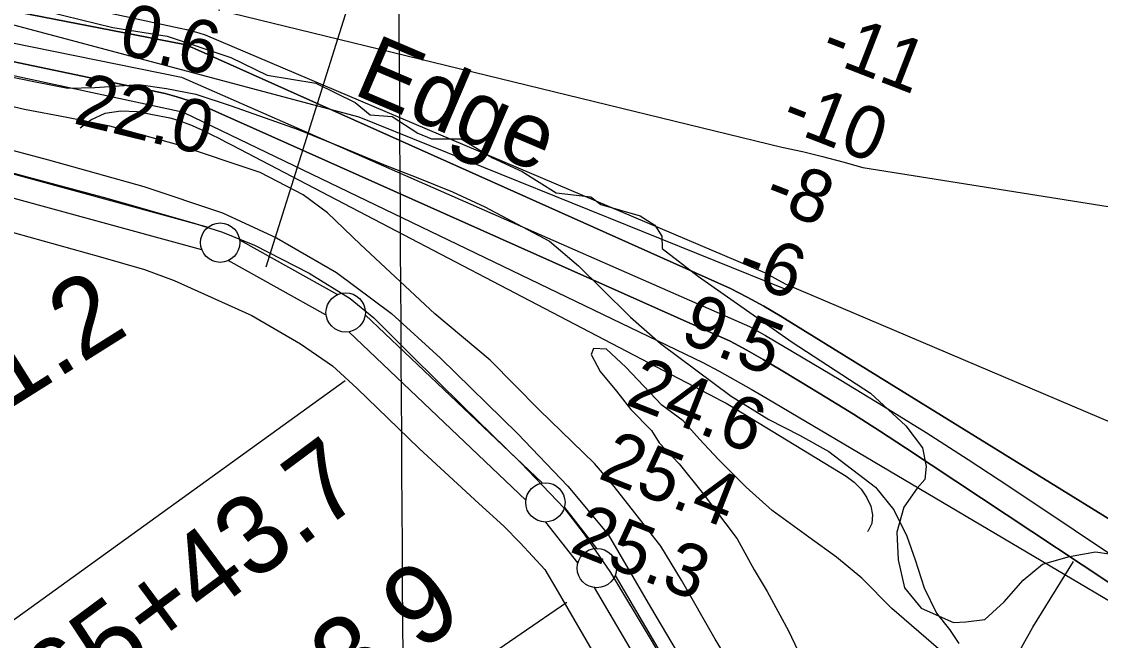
# Model space of a CAD drawing. Extents: x 3477039 to 3515015, y 546746 to 572297.
# Drawn here: x 3496548 to 3497919, y 562259 to 563045 of the extents above; entities that cross this region are included whole.
import ezdxf

# ---------------------------------------------------------------- set-up
doc = ezdxf.new("R2010")
doc.units = 0
for name, color, linetype in [('V-FLOD-BASE', 7, 'Continuous'), ('V-GRID-MAJR', 7, 'Continuous'), ('V-LEVE-TOET', 7, 'Continuous'), ('V-RIVR-EDGE', 7, 'Continuous'), ('V-RIVR-IDEN', 7, 'Continuous'), ('V-RIVR-RANG', 7, 'Continuous'), ('V-ROAD-CNTR', 7, 'Continuous'), ('V-RRAP-FSHR', 7, 'Continuous'), ('V-SITE-VEGE', 7, 'Continuous'), ('V-SURV-IDEN', 7, 'Continuous'), ('V-SURV-LINE', 7, 'Continuous'), ('V-TOPO-DPTH', 7, 'Continuous'), ('V-TOPO-MINR', 7, 'Continuous'), ('V-TOPO-SHOR', 7, 'Continuous'), ('V-TOPO-WATR', 7, 'Continuous')]:
    doc.layers.add(name, color=color, linetype=linetype)

msp = doc.modelspace()

# ---------------------------------------------------------------- linework, layer by layer
at = {"layer": 'V-FLOD-BASE'}
msp.add_lwpolyline([(3496072.208, 562978.024), (3496198.731, 562942.932), (3496343.41, 562904.79), (3496508.679, 562860.148), (3496656.299, 562821.006), (3496768.595, 562788.941), (3496803.407, 562777.941), (3496844.078, 562761.012), (3496913.6240000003, 562725.748), (3496965.506, 562693.531), (3496995.821, 562668.801), (3497043.197, 562621.384), (3497108.16, 562557.169), (3497182.41, 562484.549), (3497238.077, 562426.77), (3497262.943, 562394.213), (3497296.559, 562345.399), (3497348.136, 562259.156), (3497396.784, 562175.876), (3497451.286, 562085.197), (3497489.725, 562020.638), (3497518.917, 561971.357), (3497528.301, 561980.636)], dxfattribs=at)
at = {"layer": 'V-GRID-MAJR'}
msp.add_spline([(3497073.037565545, 555496.0515890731), (3497056.56, 558259.177), (3497020.416, 564320.132), (3496984.272, 570381.104), (3496984.251, 570384.554)], degree=3, dxfattribs=at)
at = {"layer": 'V-LEVE-TOET'}
for points in [[(3495687.304, 563022.464), (3495831.693, 563028.606), (3495926.179, 563028.921), (3495972.9590000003, 563024.707), (3496046.356, 563009.4), (3496195.292, 562971.336), (3496374.8000000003, 562924.779), (3496582.252, 562869.745), (3496703.219, 562835.785), (3496803.19, 562802.384), (3496872.115, 562770.48), (3496947.965, 562726.2880000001), (3497018.085, 562674.257), (3497080.299, 562617.46), (3497178.154, 562521.957), (3497242.06, 562455.09), (3497293.311, 562393.546), (3497347.444, 562301.365), (3497421.936, 562175.383), (3497485.5840000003, 562065.21), (3497528.424, 561986.657)], [(3495981.995, 562925.794), (3496080.275, 562901.591), (3496182.9020000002, 562873.425), (3496314.361, 562838.527), (3496447.563, 562802.304), (3496648.447, 562746.437), (3496704.343, 562730.358), (3496741.877, 562716.136), (3496840.474, 562671.81), (3496902.377, 562636.011), (3496942.8880000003, 562607.777), (3496974.216, 562579.594), (3497053.376, 562503.013), (3497129.074, 562433.013), (3497160.832, 562403.956), (3497181.703, 562382.835), (3497212.9990000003, 562348.9670000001), (3497226.856, 562325.263), (3497280.116, 562233.525), (3497366.765, 562092.598), (3497411.8170000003, 562017.9670000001), (3497436.4930000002, 561974.955), (3497448.6210000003, 561954.76)]]:
    msp.add_lwpolyline(points, dxfattribs=at)
at = {"layer": 'V-RIVR-EDGE'}
msp.add_lwpolyline([(3496560.1901922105, 563063.4036298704), (3496663.983718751, 563037.933259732), (3496732.9941397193, 563026.9567374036), (3496813.9709404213, 562999.7418065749), (3496860.1408847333, 562977.4155561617), (3496921.9489145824, 562967.0571699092), (3496971.7148589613, 562942.3207210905), (3496990.886598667, 562926.6648224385), (3497019.097324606, 562924.7940855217), (3497051.462809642, 562903.702622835), (3497068.854362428, 562896.4556989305), (3497106.6747090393, 562896.3621800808), (3497146.2366474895, 562872.2512894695), (3497184.0139457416, 562854.7484047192), (3497227.170399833, 562827.6269927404), (3497271.5824236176, 562822.714561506), (3497284.1654550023, 562813.0782211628), (3497333.9566346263, 562798.5472626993), (3497352.536957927, 562786.4947862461), (3497361.5076605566, 562772.6650917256), (3497362.0693884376, 562757.0552102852), (3497408.206675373, 562721.5218547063), (3497527.464609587, 562637.7815621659), (3497626.959387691, 562573.3005904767), (3497671.881184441, 562531.7669741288), (3497692.8227200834, 562503.4998399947), (3497697.5674111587, 562480.0753690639), (3497695.7248783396, 562463.2707794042), (3497686.092991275, 562452.4887169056), (3497669.224571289, 562428.5173623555), (3497660.14105227, 562396.7225117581), (3497661.8544400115, 562361.2990037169), (3497670.171380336, 562325.8591669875), (3497691.1188536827, 562299.9933247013), (3497732.4966052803, 562281.8812104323), (3497748.106486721, 562282.4429383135), (3497772.126827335, 562285.3851760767), (3497796.7964769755, 562308.136587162), (3497820.877679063, 562335.6920663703), (3497845.5413909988, 562356.0421856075), (3497879.7835506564, 562365.5627407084), (3497912.8161578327, 562371.484326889), (3497947.6230142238, 562366.5956464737)], dxfattribs=at)
at = {"layer": 'V-RIVR-RANG'}
msp.add_line((3496858.6666, 562733.698), (3497123.1673, 563573.0069000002), dxfattribs=at)
at = {"layer": 'V-ROAD-CNTR'}
msp.add_lwpolyline([(3496878.1762055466, 561543.768886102), (3497110.424741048, 561698.6355763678), (3497343.9712739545, 561857.336258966), (3497474.2200134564, 561930.8751118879), (3497516.53792882, 561956.562060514), (3497550.804860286, 561982.9160078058), (3497648.600664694, 562052.7898680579), (3497701.835558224, 562092.0257895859), (3497726.6265086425, 562111.6957502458), (3497751.4764589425, 562136.2327011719), (3497777.678406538, 562176.387620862), (3497832.995295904, 562276.022421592), (3497884.8031922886, 562359.22825518)], dxfattribs=at)
at = {"layer": 'V-RRAP-FSHR'}
msp.add_lwpolyline([(3496209.8331950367, 563128.6671438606), (3496976.665835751, 562924.4241996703), (3497517.9563322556, 562705.5933514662)], dxfattribs=at)
at = {"layer": 'V-SITE-VEGE'}
for points in [[(3496530.38, 562975.956), (3496565.602, 562968.901), (3496606.693, 562960.836), (3496640.978, 562961.622), (3496696.829, 562965.224), (3496732.061, 562960.129), (3496769.24, 562953.0650000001), (3496814.2120000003, 562938.121), (3496899.258, 562908.257), (3496953.005, 562886.407), (3497007.7260000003, 562863.572), (3497051.707, 562846.674), (3497095.681, 562828.799), (3497136.715, 562809.955), (3497218.744, 562766.398), (3497255.786, 562734.8470000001), (3497285.009, 562706.279), (3497322.024, 562669.829), (3497360.0330000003, 562636.316), (3497449.768, 562569.207), (3497497.595, 562539.554), (3497536.663, 562519.746), (3497573.764, 562498.969), (3497633.257, 562453.579), (3497656.6040000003, 562425.042), (3497673.066, 562391.647), (3497683.668, 562361.224), (3497695.223, 562325.9), (3497710.7120000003, 562293.491), (3497727.248, 562272.828), (3497738.903, 562255.134)], [(3497452.715, 562222.462), (3497429.423, 562260.79), (3497386.747, 562335.471), (3497360.545, 562378.712), (3497327.48, 562421.0160000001), (3497301.225, 562454.466), (3497275.924, 562483.992), (3497205.786, 562551.969), (3497143.453, 562615.004), (3497073.2660000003, 562674.167), (3496978.751, 562761.87), (3496936.861, 562802.263), (3496905.645, 562824.9670000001), (3496850.955, 562853.678), (3496743.417, 562889.545), (3496660.293, 562912.54), (3496605.503, 562923.621), (3496551.691, 562933.718), (3496511.583, 562942.76)], [(3497713.399, 562248.42), (3497653.9390000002, 562299.686), (3497615.955, 562338.098), (3497583.7830000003, 562364.724), (3497548.67, 562390.39), (3497501.843, 562423.952), (3497468.7060000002, 562453.523), (3497433.644, 562488.983), (3497409.304, 562514.585), (3497388.867, 562538.206), (3497361.5530000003, 562557.949), (3497315.788, 562606.2000000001), (3497291.429, 562628.865), (3497274.785, 562629.938), (3497271.8030000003, 562622.1190000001), (3497283.436, 562600.504), (3497303.865, 562575.904), (3497322.342, 562552.292), (3497348.6380000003, 562525.699), (3497358.345, 562509.975), (3497383.661, 562483.387), (3497412.841, 562446.982), (3497457.565, 562387.963), (3497478.8910000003, 562348.664), (3497495.387, 562321.147), (3497522.532, 562271.041), (3497554.4760000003, 562204.257)]]:
    msp.add_lwpolyline(points, dxfattribs=at)
at = {"layer": 'V-SURV-LINE'}
for points in [[(3496037.8723756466, 562988.4080392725), (3496784.9746972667, 562784.142716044)], [(3496777.0595025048, 562755.2057206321), (3496029.956636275, 562959.4711927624)], [(3496825.0244797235, 562767.8216314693), (3496949.6372057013, 562698.5999764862)], [(3496935.07870085, 562672.3692682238), (3496810.4658875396, 562741.5909717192)], [(3496984.631403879, 562672.8888537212), (3497209.4488662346, 562459.0803386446)], [(3497188.7864359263, 562437.3302986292), (3496963.9692479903, 562651.1385527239)], [(3497237.7426249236, 562427.9564077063), (3497278.558338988, 562375.9210310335)], [(3497254.940077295, 562357.4229719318), (3497214.1248192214, 562409.457767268)], [(3497302.133959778, 562341.3218390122), (3497646.563880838, 561754.9311758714)], [(3497620.6985608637, 561739.7329770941), (3497276.2689325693, 562326.1231418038)]]:
    msp.add_lwpolyline(points, dxfattribs=at)
for centre in [(3496800.28232, 562764.4068499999), (3496959.82085, 562675.7841300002), (3497213.59695, 562434.43472), (3497279.08556, 562350.9440500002)]:
    msp.add_circle(centre, 25, dxfattribs=at)
at = {"layer": 'V-TOPO-DPTH'}
for points in [[(3497951.1001583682, 562400.5103058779), (3497512.086101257, 562671.5413076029), (3497491.3229211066, 562683.5701052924), (3497470.2713532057, 562695.0867503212), (3497449.027526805, 562706.2619602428), (3496768.555811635, 563010.6883370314), (3496764.688684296, 563012.2789411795), (3496760.792792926, 563013.7921050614), (3496756.8537555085, 563015.1891085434), (3496752.8859540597, 563016.5086717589), (3496022.100627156, 563159.0706898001)], [(3496022.100627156, 563159.0706898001), (3496752.8859540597, 563016.5086717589), (3496756.8537555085, 563015.1891085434), (3496760.792792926, 563013.7921050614), (3496764.688684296, 563012.2789411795), (3496768.555811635, 563010.6883370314), (3497449.027526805, 562706.2619602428), (3497470.2713532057, 562695.0867503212), (3497491.3229211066, 562683.5701052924), (3497512.086101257, 562671.5413076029), (3497951.1001583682, 562400.5103058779)], [(3498319.7745268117, 562045.668540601), (3498313.5190530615, 562051.2428822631), (3498082.5051031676, 562230.2756945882), (3498076.1257527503, 562235.1061265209), (3498069.6767550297, 562239.8394009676), (3498063.123286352, 562244.4269391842), (3498056.5001703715, 562248.9173199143), (3497671.3673842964, 562503.7774280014), (3497638.2959532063, 562525.3273420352), (3497605.026394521, 562546.5619391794), (3497571.459644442, 562567.3235609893), (3497537.6947667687, 562587.7698659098), (3497511.1291651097, 562603.6007996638), (3497490.419214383, 562615.755113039), (3497469.603695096, 562627.7229340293), (3497448.629822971, 562639.4110164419), (3496774.9620149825, 562939.8991478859), (3496760.1951653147, 562944.9643186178), (3496745.3287497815, 562949.6977768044), (3496730.31298545, 562953.9336661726), (3495961.836846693, 563115.1532687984)], [(3496798.264202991, 563060.3077159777), (3497514.3571759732, 562885.9203614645), (3497540.223596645, 562880.2632503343), (3497565.9590105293, 562874.0936762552), (3497591.49791423, 562867.1554077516), (3497616.9058111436, 562859.7046762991), (3498389.7032243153, 562737.2775372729)], [(3496798.264202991, 563060.3077159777), (3497514.3571759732, 562885.9203614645), (3497540.223596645, 562880.2632503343), (3497565.9590105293, 562874.0936762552), (3497591.49791423, 562867.1554077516), (3497616.9058111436, 562859.7046762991), (3498389.7032243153, 562737.2775372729)]]:
    msp.add_lwpolyline(points, dxfattribs=at)
at = {"layer": 'V-TOPO-MINR'}
for points in [[(3495962.5593857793, 563206.8497661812), (3496749.5225480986, 563036.992589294), (3496757.5021655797, 563035.0802353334), (3496765.4532829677, 563033.0602953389), (3496773.361650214, 563030.8789762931), (3496781.241517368, 563028.5900712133), (3497492.154394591, 562726.3530113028), (3497505.335423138, 562719.2565741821), (3497518.400462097, 562711.9487913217), (3498210.8662024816, 562417.9298854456), (3498809.7839322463, 562018.7499259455), (3498836.3322918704, 561999.9304653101), (3498862.790504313, 561980.9860429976), (3498889.1134959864, 561961.854178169), (3499795.129970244, 561510.7892343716), (3499807.621747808, 561498.2787757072), (3499819.8414169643, 561485.4874467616), (3499910.6355924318, 561387.2314009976), (3499968.329494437, 561325.3693341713), (3500026.3989855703, 561263.865164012), (3500392.8703155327, 560889.0486487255)], [(3495964.296088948, 563134.9125580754), (3496751.2371467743, 562974.5651640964), (3497473.002544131, 562657.7323242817), (3497479.915492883, 562654.0448458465), (3497486.749094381, 562650.2123208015), (3497493.5297977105, 562646.2830980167), (3497589.178619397, 562589.5007085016), (3497643.472841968, 562556.6775003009), (3497697.405709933, 562523.2810427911), (3497750.796545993, 562489.0247113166), (3497803.8260274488, 562454.1951305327), (3498047.920982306, 562291.0600016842)], [(3495961.836846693, 563115.1532687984), (3496730.31298545, 562953.9336661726), (3496745.3287497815, 562949.6977768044), (3496760.1951653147, 562944.9643186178), (3496774.9620149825, 562939.8991478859), (3497448.629822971, 562639.4110164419), (3497469.603695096, 562627.7229340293), (3497490.419214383, 562615.755113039), (3497511.1291651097, 562603.6007996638), (3497537.6947667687, 562587.7698659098), (3497571.459644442, 562567.3235609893), (3497605.026394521, 562546.5619391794), (3497638.2959532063, 562525.3273420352), (3497671.3673842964, 562503.7774280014), (3498056.5001703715, 562248.9173199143), (3498063.123286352, 562244.4269391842), (3498069.6767550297, 562239.8394009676), (3498076.1257527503, 562235.1061265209), (3498082.5051031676, 562230.2756945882), (3498313.5190530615, 562051.2428822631), (3498319.7745268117, 562045.668540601)], [(3496006.3622241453, 563091.7372108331), (3496748.200157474, 562931.4640090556), (3496754.904706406, 562929.3111532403), (3497413.7817678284, 562612.3123601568), (3497434.3342412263, 562601.1038314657), (3497454.7933469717, 562589.7297403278), (3497475.112401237, 562578.1073055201), (3497495.338087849, 562566.3193082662), (3497989.835469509, 562274.065703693)], [(3496798.264202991, 563060.3077159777), (3497514.3571759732, 562885.9203614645), (3497540.223596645, 562880.2632503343), (3497565.9590105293, 562874.0936762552), (3497591.49791423, 562867.1554077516), (3497616.9058111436, 562859.7046762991), (3498389.7032243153, 562737.2775372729)], [(3496622.203805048, 562910.2959228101), (3496636.144251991, 562920.4585767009), (3496654.204244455, 562929.0242253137), (3496673.9788358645, 562931.9395638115), (3496694.8964932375, 562931.0880288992), (3496736.461010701, 562922.9531846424), (3496741.103116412, 562921.7148133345), (3496751.4724252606, 562918.1847953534), (3496757.7495556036, 562915.9171052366), (3496763.9640263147, 562913.4969398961), (3496770.0845075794, 562910.8480617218), (3496776.1423292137, 562908.0467083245), (3496781.324696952, 562905.5324876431), (3496789.9075728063, 562901.3215939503), (3496798.465139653, 562897.06043046), (3496806.984742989, 562892.723862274), (3496815.479037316, 562888.3370242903), (3497430.1624055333, 562567.4407016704), (3497436.7757662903, 562563.9042661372), (3497443.3403592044, 562560.2814968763), (3497449.831800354, 562556.5292270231), (3497456.27447366, 562552.6906234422), (3497596.0204015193, 562467.5391097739), (3497606.0746052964, 562459.9238100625), (3497614.870348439, 562451.2624218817), (3497621.778400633, 562441.0319009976), (3497627.4279921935, 562429.7552916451), (3497629.295909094, 562418.3612826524), (3497628.5308588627, 562407.6779660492), (3497623.8163579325, 562398.0606880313), (3497623.1482207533, 562397.2507735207)]]:
    msp.add_lwpolyline(points, dxfattribs=at)
at = {"layer": 'V-TOPO-SHOR'}
for p, q in [((3496518.674816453, 562271.4665421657), (3496959.2386911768, 562589.2503206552)), ((3496713.6784987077, 561946.4604050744), (3497240.9106766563, 562307.578335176))]:
    msp.add_line(p, q, dxfattribs=at)
at = {"layer": 'V-TOPO-WATR'}
msp.add_lwpolyline([(3496022.100627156, 563159.0706898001), (3496752.8859540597, 563016.5086717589), (3496756.8537555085, 563015.1891085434), (3496760.792792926, 563013.7921050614), (3496764.688684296, 563012.2789411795), (3496768.555811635, 563010.6883370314), (3497449.027526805, 562706.2619602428), (3497470.2713532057, 562695.0867503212), (3497491.3229211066, 562683.5701052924), (3497512.086101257, 562671.5413076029), (3497951.1001583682, 562400.5103058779)], dxfattribs=at)

# ---------------------------------------------------------------- texts
at = {"layer": 'V-RIVR-IDEN'}
msp.add_text('Edge', height=83.0000000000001, rotation=336.89596722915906, dxfattribs=at).set_placement((3496967.2996953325, 562953.9571535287))
at = {"layer": 'V-RIVR-RANG'}
for s, height, rotation, p in [('0.6', 67.00000000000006, 346.5977222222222, (3496668.9788965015, 563005.0178399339)), ('-11', 67.00000000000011, 338.8322777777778, (3497560.382700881, 562999.380447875)), ('22.0', 67.00000000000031, 346.31832571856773, (3496612.1824589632, 562916.3618577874)), ('-10', 67.00000000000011, 338.8322777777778, (3497510.2667295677, 562911.5514814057)), ('-8', 67.00000000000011, 338.8322777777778, (3497488.439645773, 562812.7676960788)), ('-6', 67.00000000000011, 338.8322777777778, (3497452.5906090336, 562719.4141948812)), ('9.5', 67, 338.54832571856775, (3497382.5503772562, 562639.7554557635)), ('24.6', 67, 338.54832571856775, (3497313.5580048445, 562559.4227641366)), ('25.4', 67, 338.54832571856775, (3497278.9355507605, 562465.5844847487)), ('25.3', 67, 338.54832571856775, (3497242.59555076, 562372.4214847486))]:
    msp.add_text(s, height=height, rotation=rotation, dxfattribs=at).set_placement(p)
at = {"layer": 'V-SURV-IDEN'}
for s, height, rotation, p in [('1663+61.2', 100.0000000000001, 32.15412102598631, (3496148.833321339, 562311.7368322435)), ('1665+43.7', 100.00000000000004, 36.58823544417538, (3496479.6088524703, 562063.2364698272)), ('1668+93.9', 100.00000000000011, 35.6489073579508, (3496597.3719933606, 561916.2511490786))]:
    msp.add_text(s, height=height, rotation=rotation, dxfattribs=at).set_placement(p)

doc.saveas('drawing.dxf')
